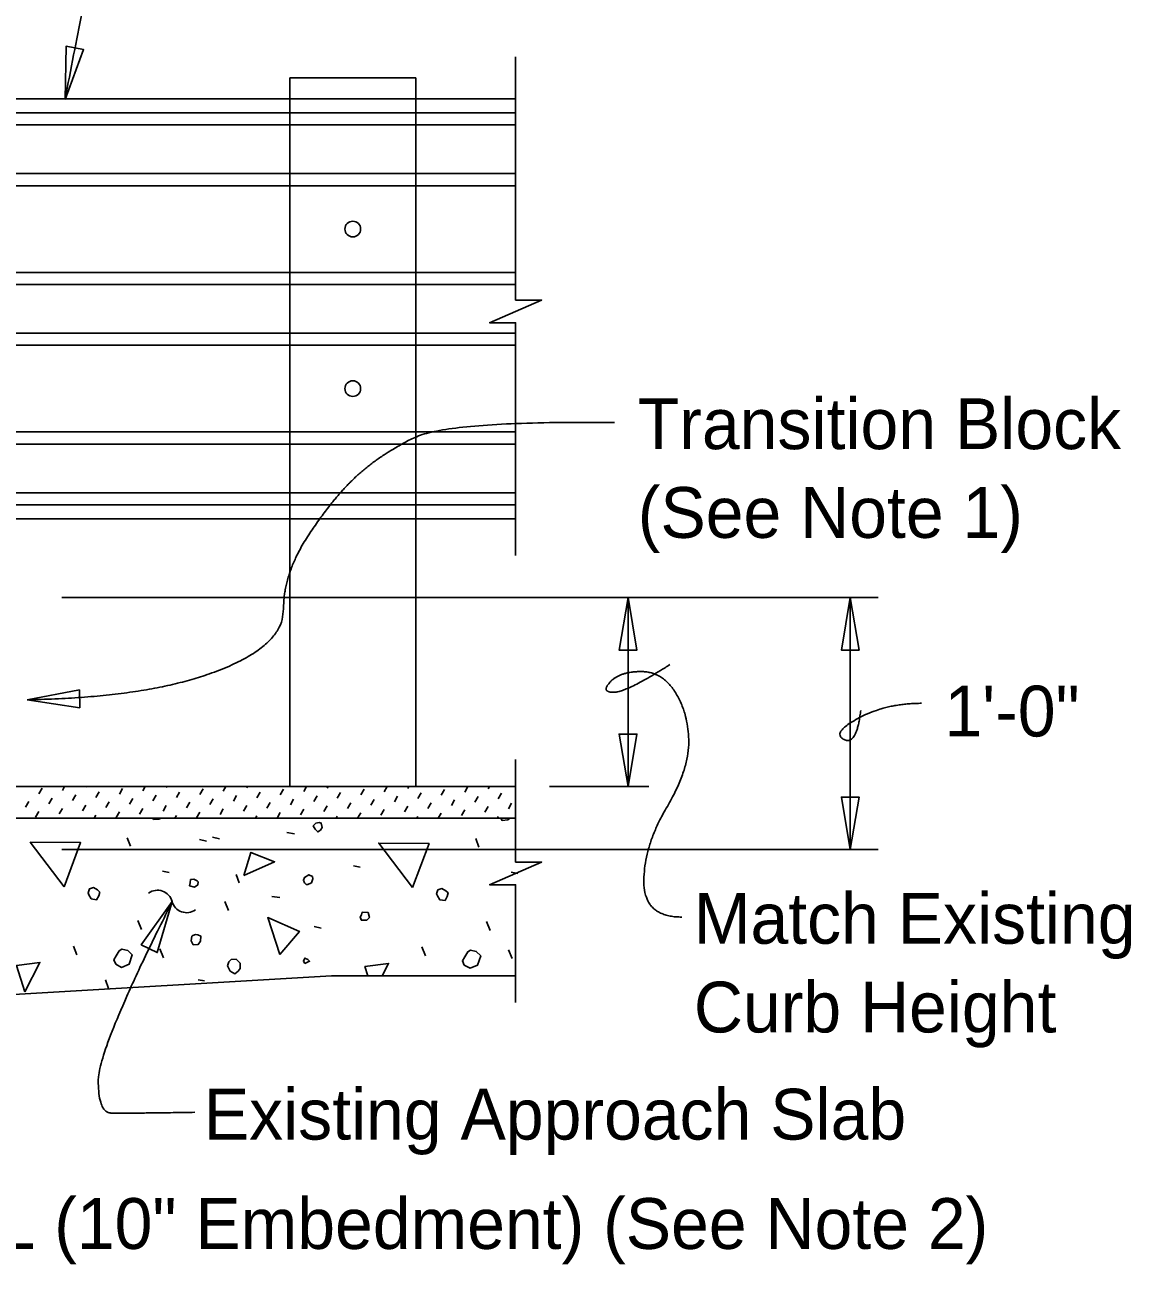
# Model space of a CAD drawing. Extents: x 0 to 41.1, y 0 to 25.9.
# Drawn here: x 13.119 to 17.51, y 5.224 to 10.142 of the extents above; entities that cross this region are included whole.
import ezdxf

# ---------------------------------------------------------------- set-up
doc = ezdxf.new("R2010")
doc.units = 0
for name, color, linetype in [('Dimension', 7, 'Continuous'), ('ExistSuperStruct', 7, 'Continuous'), ('Miscellaneous', 7, 'Continuous'), ('SteelMisc_h', 7, 'Continuous'), ('TextStructures', 7, 'Continuous')]:
    doc.layers.add(name, color=color, linetype=linetype)

msp = doc.modelspace()

# ---------------------------------------------------------------- linework, layer by layer
at = {"layer": 'Dimension'}
for p, q in [((13.2657, 7.869), (16.5054, 7.869)), ((15.5125, 7.869), (15.5125, 7.119)), ((16.3947, 7.8691), (16.3947, 6.8691)), ((15.2005, 7.119), (15.5952, 7.119)), ((13.2657, 6.869), (16.5054, 6.869))]:
    msp.add_line(p, q, dxfattribs=at)
for points in [[(13.2782, 9.8455), (13.3519, 10.0434), (13.2826, 10.0567)], [(15.5125, 7.869), (15.4772, 7.6607), (15.5478, 7.6607)], [(16.3947, 7.8691), (16.3594, 7.6608), (16.4299, 7.6608)], [(13.128, 7.464), (13.3368, 7.4322), (13.3356, 7.5028)], [(15.5125, 7.119), (15.5478, 7.3272), (15.4772, 7.3272)], [(16.3947, 6.8691), (16.4299, 7.0774), (16.3594, 7.0774)], [(13.7038, 6.6633), (13.5807, 6.4917), (13.6441, 6.4607)]]:
    msp.add_lwpolyline(points, close=True, dxfattribs=at)
for points in [[(15.0664, 8.0366), (15.0664, 8.9592), (14.9631, 8.9592), (15.0664, 9.0042), (15.1698, 9.0492), (15.0664, 9.0492), (15.0664, 10.014)], [(15.0664, 6.2625), (15.0664, 6.7297), (14.9631, 6.7297), (15.0664, 6.7747), (15.1698, 6.8197), (15.0664, 6.8197), (15.0664, 7.2271)]]:
    msp.add_lwpolyline(points, dxfattribs=at)
for centre, start, end in [((13.6454, 6.6485), 14.5413, 126.2686), ((13.7608, 6.6785), 194.5413, 306.2686)]:
    msp.add_arc(centre, 0.0596, start, end, dxfattribs=at)
for points in [[(13.787, 10.8282), (13.6668, 10.8282), (13.5361, 10.8211), (13.4301, 10.6409), (13.2781, 9.8455)], [(15.459, 8.5636), (14.7975, 8.5705), (14.5233, 8.4333), (14.3404, 8.2621), (14.1448, 7.9647), (14.1448, 7.6752), (13.5973, 7.4717), (13.1279, 7.4639)], [(15.7263, 6.6015), (15.5755, 6.6015), (15.5755, 6.8827), (15.7537, 7.1845), (15.7537, 7.4041), (15.6509, 7.5755), (15.4795, 7.5755), (15.4041, 7.4932), (15.5069, 7.4932), (15.6783, 7.603)], [(16.4361, 7.4216), (16.4201, 7.2802), (16.3188, 7.3322), (16.5362, 7.4496), (16.6775, 7.4496)], [(13.7936, 5.8268), (13.511, 5.8223), (13.4104, 5.8255), (13.4104, 6.0812), (13.7038, 6.6633)]]:
    msp.add_open_spline(points, degree=2, dxfattribs=at)
at = {"layer": 'ExistSuperStruct'}
for p, q in [((9.1157, 7.119), (15.0664, 7.119)), ((10.9656, 6.9939), (15.0664, 6.9939)), ((10.1157, 6.119), (14.3357, 6.369)), ((14.3357, 6.369), (15.0664, 6.369))]:
    msp.add_line(p, q, dxfattribs=at)
at = {"layer": 'Miscellaneous'}
for p, q in [((14.1703, 9.9314), (14.1703, 7.119)), ((14.1703, 9.9314), (14.6703, 9.9314)), ((14.6703, 9.9314), (14.6703, 7.119)), ((7.5427, 9.7926), (15.0664, 9.7926)), ((7.5427, 9.7444), (15.0664, 9.7444)), ((7.5427, 9.5515), (15.0664, 9.5515)), ((7.5427, 9.5033), (15.0664, 9.5033)), ((7.5427, 9.1594), (15.0664, 9.1594)), ((7.5427, 9.1111), (15.0664, 9.1111)), ((7.5427, 8.9183), (15.0664, 8.9183)), ((7.5427, 8.8702), (15.0664, 8.8702)), ((7.5427, 8.5262), (15.0664, 8.5262)), ((7.5427, 8.478), (15.0664, 8.478)), ((7.5427, 8.2852), (15.0664, 8.2852)), ((7.5427, 8.237), (15.0664, 8.237)), ((13.1745, 7.0907), (13.1874, 7.1131)), ((13.2676, 7.1036), (13.2764, 7.119)), ((13.3076, 7.0636), (13.3206, 7.086)), ((13.3607, 7.1166), (13.362, 7.119)), ((13.4007, 7.0765), (13.4137, 7.0989)), ((13.4938, 7.0895), (13.5068, 7.1119)), ((13.587, 7.1025), (13.5965, 7.119)), ((13.627, 7.0624), (13.64, 7.0848)), ((13.6801, 7.1154), (13.6821, 7.119)), ((13.7201, 7.0754), (13.7331, 7.0977)), ((13.8132, 7.0883), (13.8262, 7.1107)), ((13.9063, 7.1013), (13.9166, 7.119)), ((13.9464, 7.0612), (13.9594, 7.0836)), ((13.9994, 7.1142), (14.0022, 7.119)), ((14.0395, 7.0742), (14.0525, 7.0966)), ((14.1326, 7.0871), (14.1456, 7.1095)), ((14.2257, 7.1001), (14.2366, 7.119)), ((14.2658, 7.06), (14.2787, 7.0824)), ((14.3188, 7.1131), (14.3222, 7.119)), ((14.3589, 7.073), (14.3718, 7.0954)), ((14.452, 7.086), (14.4649, 7.1084)), ((14.5451, 7.0989), (14.5567, 7.119)), ((14.5852, 7.0589), (14.5981, 7.0813)), ((14.6382, 7.1119), (14.6423, 7.119)), ((14.6783, 7.0718), (14.6912, 7.0942)), ((14.7714, 7.0848), (14.7843, 7.1072)), ((14.8645, 7.0977), (14.8767, 7.119)), ((14.9576, 7.1107), (14.9623, 7.119)), ((14.9976, 7.0706), (15.0106, 7.093)), ((13.1214, 7.0376), (13.1344, 7.06)), ((13.2145, 7.0506), (13.2275, 7.073)), ((13.2546, 7.0105), (13.2676, 7.0329)), ((13.3477, 7.0235), (13.3607, 7.0459)), ((13.4408, 7.0365), (13.4538, 7.0589)), ((13.5339, 7.0494), (13.5469, 7.0718)), ((13.6671, 7.0223), (13.6801, 7.0447)), ((13.7602, 7.0353), (13.7732, 7.0577)), ((13.8533, 7.0483), (13.8663, 7.0706)), ((13.9865, 7.0211), (13.9994, 7.0435)), ((14.0796, 7.0341), (14.0925, 7.0565)), ((14.1727, 7.0471), (14.1856, 7.0695)), ((14.3058, 7.02), (14.3188, 7.0424)), ((14.3989, 7.0329), (14.4119, 7.0553)), ((14.492, 7.0459), (14.505, 7.0683)), ((14.6252, 7.0188), (14.6382, 7.0412)), ((14.7183, 7.0318), (14.7313, 7.0541)), ((14.8114, 7.0447), (14.8244, 7.0671)), ((14.9045, 7.0577), (14.9175, 7.0801)), ((14.9446, 7.0176), (14.9576, 7.04)), ((15.0377, 7.0306), (15.0507, 7.053)), ((13.1615, 6.9976), (13.1745, 7.02)), ((13.3939, 6.9939), (13.4007, 7.0058)), ((13.4809, 6.9964), (13.4938, 7.0188)), ((13.574, 7.0094), (13.587, 7.0318)), ((13.7139, 6.9939), (13.7201, 7.0046)), ((13.8003, 6.9952), (13.8132, 7.0176)), ((13.8934, 7.0082), (13.9063, 7.0306)), ((14.034, 6.9939), (14.0395, 7.0035)), ((14.1196, 6.994), (14.1326, 7.0164)), ((14.2127, 7.007), (14.2257, 7.0294)), ((14.354, 6.9939), (14.3589, 7.0023)), ((14.4396, 6.9939), (14.452, 7.0153)), ((14.5321, 7.0058), (14.5451, 7.0282)), ((14.6741, 6.9939), (14.6783, 7.0011)), ((14.7597, 6.9939), (14.7714, 7.0141)), ((14.8515, 7.0046), (14.8645, 7.027)), ((14.9942, 6.9939), (14.9976, 6.9999)), ((14.1591, 6.9374), (14.1892, 6.9321)), ((13.5377, 6.8826), (13.5254, 6.9162)), ((13.8118, 6.9092), (13.84, 6.9021)), ((13.8635, 6.9184), (13.8917, 6.9114)), ((14.921, 6.8791), (14.9087, 6.9127)), ((14.4225, 6.8049), (14.449, 6.7996)), ((13.665, 6.7836), (13.6915, 6.7783)), ((13.9695, 6.7372), (13.9572, 6.7708)), ((15.0483, 6.7801), (15.0748, 6.7748)), ((13.9271, 6.6276), (13.913, 6.663)), ((14.099, 6.6829), (14.1308, 6.6793)), ((13.5819, 6.5521), (13.5678, 6.5874)), ((14.267, 6.5644), (14.2952, 6.5574)), ((14.9652, 6.5485), (14.9511, 6.5839)), ((13.3256, 6.4513), (13.3115, 6.4867)), ((13.669, 6.4403), (13.6549, 6.4756)), ((14.7089, 6.4478), (14.6948, 6.4831)), ((15.0523, 6.4367), (15.0381, 6.4721)), ((13.4511, 6.3187), (13.4388, 6.3523)), ((13.8069, 6.3519), (13.8316, 6.3483))]:
    msp.add_line(p, q, dxfattribs=at)
for points in [[(13.6264, 6.9939), (13.6297, 6.9887), (13.6527, 6.9905), (13.6561, 6.9939)], [(15.0075, 6.9939), (15.013, 6.9852), (15.0359, 6.9869), (15.0429, 6.9939)], [(14.2705, 6.9498), (14.2811, 6.9392), (14.2917, 6.9463), (14.2988, 6.9569), (14.2952, 6.9746), (14.2864, 6.9763), (14.274, 6.9746), (14.2634, 6.964), (14.2705, 6.9498)], [(13.2744, 6.7218), (13.14, 6.8985), (13.3398, 6.8968), (13.2744, 6.7218)], [(14.6576, 6.7182), (14.5233, 6.895), (14.723, 6.8932), (14.6576, 6.7182)], [(13.9876, 6.766), (14.0159, 6.8579), (14.1096, 6.8208), (13.9876, 6.766)], [(13.7729, 6.7253), (13.7923, 6.72), (13.8047, 6.7288), (13.8064, 6.7412), (13.8029, 6.7448), (13.7888, 6.7518), (13.7764, 6.7501), (13.7746, 6.7377), (13.7729, 6.7253)], [(14.2351, 6.7306), (14.2422, 6.7306), (14.2563, 6.7377), (14.2616, 6.7536), (14.2599, 6.7624), (14.2457, 6.7695), (14.2281, 6.7589), (14.2245, 6.7483), (14.2281, 6.7377), (14.2351, 6.7306)], [(13.3733, 6.69), (13.3822, 6.674), (13.4034, 6.6705), (13.4122, 6.6864), (13.4158, 6.7006), (13.4069, 6.7094), (13.391, 6.7182), (13.3751, 6.7129), (13.3698, 6.697), (13.3733, 6.69)], [(14.7566, 6.6864), (14.7655, 6.6705), (14.7867, 6.667), (14.7955, 6.6829), (14.7991, 6.697), (14.7902, 6.7059), (14.7743, 6.7147), (14.7584, 6.7094), (14.7531, 6.6935), (14.7566, 6.6864)], [(14.1304, 6.4526), (14.0827, 6.5994), (14.2082, 6.5446), (14.1304, 6.4526)], [(14.4543, 6.5892), (14.4755, 6.5892), (14.4862, 6.5998), (14.4809, 6.6192), (14.4579, 6.621), (14.4543, 6.6104), (14.449, 6.6016), (14.4543, 6.5892), (14.4508, 6.5927)], [(13.7786, 6.5074), (13.7874, 6.4915), (13.8069, 6.4933), (13.8157, 6.5057), (13.8175, 6.5251), (13.8051, 6.5304), (13.7963, 6.5322), (13.7857, 6.5286), (13.7821, 6.5251), (13.7786, 6.5074)], [(13.4794, 6.4142), (13.5024, 6.4018), (13.5324, 6.4142), (13.5448, 6.4513), (13.5271, 6.469), (13.5042, 6.4743), (13.4936, 6.4672), (13.4812, 6.4478), (13.4723, 6.4319), (13.4794, 6.4142)], [(14.8627, 6.4106), (14.8857, 6.3983), (14.9157, 6.4106), (14.9281, 6.4478), (14.9104, 6.4654), (14.8874, 6.4707), (14.8768, 6.4637), (14.8645, 6.4442), (14.8556, 6.4283), (14.8627, 6.4106)], [(13.1188, 6.3046), (13.0852, 6.4089), (13.1789, 6.4213), (13.1188, 6.3046)], [(13.9236, 6.4084), (13.9342, 6.3872), (13.9518, 6.3766), (13.966, 6.3872), (13.9731, 6.3978), (13.9731, 6.419), (13.9572, 6.435), (13.9377, 6.4332), (13.9289, 6.4243), (13.9236, 6.4084)], [(14.2294, 6.4173), (14.2488, 6.4261), (14.2418, 6.4332), (14.2294, 6.4385), (14.2241, 6.4261), (14.2294, 6.4173)], [(14.4802, 6.369), (14.4685, 6.4053), (14.5622, 6.4177), (14.5371, 6.369)], [(14.3382, 6.369), (14.3372, 6.3695), (14.3358, 6.369)]]:
    msp.add_lwpolyline(points, dxfattribs=at)
at = {"layer": 'SteelMisc_h'}
for p, q in [((15.0664, 9.8481), (7.5427, 9.8481)), ((15.0664, 8.1814), (7.5427, 8.1814))]:
    msp.add_line(p, q, dxfattribs=at)
for centre in [(14.4203, 9.3313), (14.4203, 8.6982)]:
    msp.add_circle(centre, 0.0312, dxfattribs=at)

# ---------------------------------------------------------------- texts
at = {"layer": 'Dimension'}
for s, p in [('Transition Block', (15.5514, 8.458)), ('(See Note 1)', (15.5514, 8.106)), ('Match Existing ', (15.774, 6.4957)), ('Curb Height', (15.774, 6.1437))]:
    msp.add_text(s, height=0.2016, dxfattribs=at).set_placement(p)
at = {"layer": 'TextStructures'}
for s, p in [('1\'-0"', (16.7683, 7.318)), ('Existing Approach Slab', (13.8291, 5.7186)), ('Dowel Bars 4L (10" Embedment) (See Note 2)', (11.4074, 5.2848))]:
    msp.add_text(s, height=0.2016, dxfattribs=at).set_placement(p)

doc.saveas('drawing.dxf')
